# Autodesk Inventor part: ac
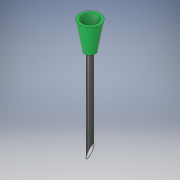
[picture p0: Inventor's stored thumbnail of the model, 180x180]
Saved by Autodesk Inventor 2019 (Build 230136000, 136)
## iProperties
Created: 2020-11
Part Number: ac
Material: ABS Plastic
Document SubType Name: Modeling
Designer: bianc
Density: 1.06 g/cm^3
Appearance: Smooth - White
Author: bianc
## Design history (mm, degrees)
sketch "Sketch1"
  geometry: L1 (0, 30)-(1, 30); L2 (0, 0)-(0, 43.102); L3 (1, 30)-(2.367, 37.75); L4 (2.367, 37.75)-(3.128, 37.75); L5 (3.128, 37.75)-(1.629, 29.25); L6 (1.629, 29.25)-(0, 29.25); L7 (0, 30)-(0, 29.25)
  constraints: 14 end point, 1 horizontal, 1 perpendicular, 1 point on line, 1 vertical
  dimensions: "d0" = 30 distance from line of L2.start L1; "d2" = 100 deg angle of L3 L1; "d4" = 1 distance of L1.start L1.end; "d5" = 0.75 distance between parallel lines of L3 L5; "d6" = 8.5 distance between parallel lines of L6 L4
revolve "Revolution1" sketch "Sketch1" stored, may be unused: angle "d7" = 90 deg
workplane "Work Plane1"
sketch "Sketch2"
  geometry: L1 (29.25, -0.8)-(0, -0.8); L2 (29.25, -0.9)-(0, -0.9); L3 (0, -0.8)-(0, -0.9); L4 (29.25, 1.629)-(29.25, -1.629) reference; L5 (29.25, -0.8)-(29.25, -0.9); L6 (29.25, 0)-(0, 0)
  constraints: 10 end point, 2 horizontal, 2 point on line, 1 collinear, 1 midpoint, 1 parallel, 1 vertical
  dimensions: "d8" = 0.8 distance from line of L6.end L1; "d9" = 0.1 distance between parallel lines of L1 L2
revolve "Revolution2" sketch "Sketch2" stored, may be unused: angle "d10" = 90 deg
sketch "Sketch3"
  geometry: 1 further point
sketch "Sketch4"
  geometry: L1 (0, 0.9)-(0, -0.9) reference; L2 (0, 0.9)-(0, -1.983); L3 (0, -1.983)-(7.922, -1.983); L4 (7.922, -1.983)-(0, 0.9); 1 further point
  constraints: 6 end point, 1 perpendicular, 1 vertical
  dimensions: "d13" = 70 deg angle of L2 L4
extrude "Extrusion1" cut sketch "Sketch4" stored distance "d14" = 10; taper "d15" = 0 deg
sketch "Sketch5"
  geometry: 1 further point
hole "Hole1" sketch "Sketch5" at (0, 0) diameter "d16" = 0.8; stored, may be unused: countersink angle "d20" = 90 deg, drill point angle "d22" = 118 deg; dims "d17" = 6, "d18" = 4, "d19" = 2, "d21" = 8
body "Solid1"
